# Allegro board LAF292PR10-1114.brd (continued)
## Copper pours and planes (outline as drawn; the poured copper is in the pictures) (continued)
+VREFCA on IN1 (solid shape): outline of 589 points within 136.57,34.88 153.97,38.31
+VREFDQ_A on BOTTOM (solid shape): 92.5,42.5 92.97,42.5 93.09,42.63 93.6,42.63 93.6,42.63 93.68,42.55 93.68,40.8 93.6,40.73 93.13,40.73 92.63,41.23 91.3,41.23 91.22,41.27 91.2,41.36 91.22,41.46 91.23,41.56 91.23,42.55 91.23,42.63 91.36,42.76 92.25,42.76
+VREFDQ_A on IN3 (solid shape): outline of 972 points within 92.5,33.37 119.93,43.77
BST_3V on TOP (solid shape): 73.89,43.19 73.89,42.33 73.81,42.25 72.89,42.25 72.73,42.09 71.75,42.09 71.61,42.23 71.61,42.92 71.95,43.27 73.82,43.27
BST_3V on BOTTOM (solid shape): 72.98,43.31 72.98,43.16 72.94,43.12 72.91,43.08 72.91,42.27 72.71,42.08 71.71,42.08 71.61,42.18 71.61,42.94 72.05,43.38 72.9,43.38
BST_5V on TOP (solid shape): 50.59,69.81 50.59,68.54 50.46,68.41 49.45,68.41 49.32,68.54 49.32,69.55 49.7,69.94 50.46,69.94
BST_5V on BOTTOM (solid shape): 51.13,70.25 51.13,70.11 51.11,70.07 51.09,70.02 50.91,69.83 50.91,69.45 50.78,69.33 49.57,69.33 49.48,69.41 49.48,70.06 49.73,70.31 51.08,70.31
BST_+1VALWP on BOTTOM (solid shape): 59.92,71.73 61.34,71.73 61.43,71.64 61.43,71.52 61.32,71.41 60.3,71.41 59.99,71.09 59.35,71.09 59.28,71.16 59.28,71.72 59.31,71.75 59.9,71.75
BST_+1VALWP_C on BOTTOM (solid shape): 58.95,71.74 58.95,71.07 59.04,70.97 59.04,70.37 58.93,70.25 58.48,70.25 58.34,70.39 58.34,71.72 58.46,71.84 58.84,71.84
CPU_B+ on TOP (solid shape): 82.03,65.47 82.03,65.14 81.33,64.44 81.33,63.69 81.46,63.57 81.46,62.52 81.34,62.4 79.4,62.4 79.26,62.54 79.26,65.6 80.39,66.73 80.78,66.73
CPU_B+ on TOP (solid shape): 90.49,80.32 92.52,80.32 92.64,80.19 92.64,77.27 92.44,77.07 90.97,77.07 90.64,76.73 90.64,76.72 90.44,76.53 90.44,74.22 90.19,73.98 88.63,73.98 88.41,74.19 88.41,79.67 89.07,80.32 90.49,80.32
CPU_B+ on BOTTOM (solid shape): 92.65,80.21 92.65,78.07 91.63,77.05 90.85,77.05 90.4,76.61 90.4,73.98 89.26,73.98 89.24,74 89.24,75.35 89.01,75.59 88.17,75.59 88.05,75.71 88.05,77.39 88.04,77.39 88.04,78 87.82,78.23 86.5,78.23 83.93,75.65 83.93,73.23 83.46,72.77 80.56,72.77 80.49,72.83 80.49,76.07 83.5,79.09 83.52,79.09 83.52,79.1 84.74,80.32 92.54,80.32
CPU_B+ on BOTTOM (solid shape): outline of 124 points within 66.84,54.04 85.89,67.41
CPU_B+ on IN1 (solid shape): 90.45,78.36 90.45,74.23 90.2,73.98 89.15,73.98 89.05,74.08 89.05,78.68 89.14,78.76 90.05,78.76
CPU_B+ on IN2 (solid shape): 90.45,78.36 90.45,74.23 90.2,73.98 89.16,73.98 89.05,74.08 89.05,78.68 89.14,78.76 90.05,78.76
CPU_B+ on IN3 (solid shape): 90.45,78.36 90.45,74.23 90.2,73.98 89.15,73.98 89.05,74.07 89.05,78.68 89.14,78.76 90.05,78.76
CPU_B+ on IN4 (solid shape): outline of 373 points within 77.56,62.4 90.64,79.33
DCIN_ISL9538 on TOP (solid shape): 54.24,34.89 54.24,34.1 53.62,33.49 53.38,33.49 53.26,33.61 53.26,34.12 54.07,34.93 54.2,34.93
GPU_B+ on TOP (solid shape): 84.54,58.67 87.12,58.67 88.08,59.63 90.43,59.63 90.65,59.41 90.65,58.4 90.5,58.25 89.33,58.25 89.14,58.06 89.14,57.16 88.84,56.86 82.96,56.86 81.65,58.18 77.76,58.18 77.52,58.42 77.52,59.43 77.72,59.63 83.59,59.63
GPU_B+ on BOTTOM (solid shape): 76.53,60.04 78.05,60.04 78.58,59.51 78.58,59.5 80.06,58.03 81.26,58.03 81.87,58.63 87.1,58.63 87.2,58.73 87.2,58.74 88.08,59.62 90.38,59.62 90.54,59.46 90.54,58.33 90.46,58.25 89.14,58.25 88.97,58.08 88.97,57.26 88.06,56.36 86.44,56.36 86.44,57.16 85.68,57.16 85.68,56.36 82.36,56.36 81.96,55.96 77.7,55.96 73.76,59.9 75.11,61.25 75.32,61.25
GPU_B+ on IN1 (solid shape): 86.21,59.44 90.5,59.44 90.65,59.29 90.65,58.4 90.46,58.21 77.86,58.21 77.61,58.46 77.61,59.32 77.73,59.44 86.21,59.44
GPU_B+ on IN2 (solid shape): 86.21,59.44 90.53,59.44 90.64,59.32 90.64,58.4 90.46,58.21 77.86,58.21 77.61,58.46 77.61,59.32 77.73,59.44 86.21,59.44
GPU_B+ on IN3 (solid shape): 86.21,59.44 90.54,59.44 90.63,59.35 90.63,58.42 90.43,58.21 77.86,58.21 77.61,58.46 77.61,59.32 77.73,59.44 86.21,59.44
GPU_B+ on IN4 (solid shape): 86.21,59.44 90.52,59.44 90.63,59.33 90.63,58.39 90.45,58.21 77.86,58.21 77.61,58.46 77.61,59.32 77.73,59.44 86.21,59.44
GT_SNUB on TOP (solid shape): 93.36,63.71 93.36,63.24 96.21,60.39 96.21,58.76 96.12,58.68 95.18,58.68 94.1,59.76 94.1,61.1 92.15,63.05 92.15,63.7 92.28,63.83 93.24,63.83
GT_SW on TOP (solid shape): 97.44,61.62 97.44,60.86 97.76,60.54 98.79,60.54 98.9,60.43 98.9,58.73 98.83,58.67 97.8,58.67 96.34,60.13 96.34,61.64 96.47,61.77 97.3,61.77
GT_SW on BOTTOM (solid shape): 95.44,63.91 96.09,63.91 97.79,62.21 97.79,58.82 96.83,58.82 96.83,57.96 97.77,57.96 97.77,56.57 95.41,56.57 95.32,56.67 95.32,59.97 94.64,60.65 92.82,60.65 92.82,60.65 92.65,60.65 92.64,60.66 92.64,61.93 92.45,62.12 88.67,62.12 88.63,62.15 88.63,63.28 88.96,63.61 90.08,63.61 90.4,63.93 95.42,63.93
IA_SNUB1 on BOTTOM (solid shape): 90.94,83.24 90.94,81.57 90.87,81.5 89.09,81.5 88.89,81.7 88.89,83.13 89.07,83.31 90.88,83.31
IA_SNUB2 on BOTTOM (solid shape): 82.98,71.63 82.98,69.27 82.8,69.09 81.57,69.09 81.37,69.28 81.37,71.67 81.48,71.77 82.83,71.77
IA_SW1 on BOTTOM (solid shape): 93.67,83.12 93.67,82.44 94.86,81.26 97.51,81.26 97.51,79.65 97.31,79.45 97.31,78.18 96.36,78.18 96.36,77.29 97.31,77.29 97.31,71.99 95.79,70.47 92.07,70.47 91.59,70.94 91.59,71.87 91.63,71.91 92.82,71.91 93.06,72.15 93.06,75.79 93.2,75.94 93.84,75.94 94.88,76.97 94.88,79.74 94.88,79.95 93.26,81.56 92.59,81.56 92.55,81.6 92.55,83.2 92.59,83.25 93.54,83.25
IA_SW2 on BOTTOM (solid shape): 85.33,71.64 85.33,70.5 85.54,70.29 85.55,70.29 85.59,70.25 88.06,70.25 88.13,70.24 88.2,70.25 88.27,70.25 88.31,70.29 88.35,70.29 88.45,70.39 88.77,70.39 89.36,69.8 90.45,69.8 91.46,68.79 93.06,68.79 93.06,67.44 92.11,67.44 92.11,66.62 93.06,66.62 93.06,65.24 92.96,65.15 90.39,65.15 90.24,65.3 90.24,67.18 89.93,67.48 88.98,67.48 88.83,67.33 88,67.33 87.96,67.38 87.96,68.64 87.81,68.78 84.08,68.78 83.96,68.9 83.96,71.72 84.09,71.84 85.13,71.84
INT_SPK_L+ on TOP (solid shape): 291.49,25.25 291.49,24.78 291.36,24.65 289.5,24.65 289.43,24.57 288.87,24.57 288.84,24.6 288.84,25.23 288.97,25.36 291.38,25.36
INT_SPK_L+ on TOP (solid shape): 268.27,40.13 268.27,39.18 267.5,38.41 267.5,37.55 267.45,37.5 267.33,37.5 267.23,37.6 267.23,38.59 267.76,39.12 267.76,40.19 267.82,40.26 268.14,40.26
INT_SPK_L+ on IN1 (solid shape): 291.51,25.23 291.51,24.6 291.38,24.47 289.48,24.47 289.35,24.34 288.97,24.34 288.84,24.47 288.84,25.23 288.97,25.36 291.38,25.36
INT_SPK_L+ on IN1 (solid shape): 268.29,40.19 268.29,39.07 267.61,38.39 267.61,37.5 267.45,37.35 266.92,37.35 266.79,37.47 266.79,38.54 266.9,38.64 267.38,38.64 267.76,39.02 267.76,40.14 267.89,40.27 268.22,40.27
INT_SPK_L- on TOP (solid shape): 267.63,39.96 267.63,39.33 267.1,38.79 267.1,37.55 267.05,37.5 266.9,37.5 266.84,37.55 266.84,38.85 267.12,39.12 267.12,39.96 267.25,40.09 267.5,40.09
INT_SPK_L- on TOP (solid shape): 291.23,22.67 291.23,22.22 291.32,22.13 291.32,21.26 291.14,21.08 290.93,21.08 290.89,21.12 290.89,21.4 290.87,21.55 290.83,21.68 290.83,21.69 290.83,22 290.27,22.56 289.04,22.56 288.84,22.77 288.84,23.48 288.94,23.58 290.32,23.58
INT_SPK_L- on IN1 (solid shape): 291.46,22 291.46,21.23 291.35,21.11 289.51,21.11 289.38,21.24 289.38,22 289.63,22.25 291.21,22.25
INT_SPK_L- on IN1 (solid shape): 267.63,40.47 267.63,39.1 267.48,38.95 267.1,38.95 267,39.05 267,39.96 266.87,40.09 265.6,40.09 265.47,40.22 265.47,41.11 265.6,41.23 266.87,41.23
INT_SPK_R+ on TOP (solid shape): 299,25.1 299,23.33 297.86,23.33 297.86,25.17 297.92,25.23 298.87,25.23
INT_SPK_R+ on TOP (solid shape): 266.21,39.61 266.21,38.69 266.29,38.62 266.29,37.58 266.21,37.5 266.16,37.5 266.06,37.6 266.06,38.39 265.73,38.72 265.73,39.58 265.85,39.71 266.11,39.71
INT_SPK_R+ on IN2 (solid shape): 299,25.1 299,24.22 298.87,24.09 297.1,24.09 296.97,24.22 296.97,25.1 297.1,25.23 298.87,25.23
INT_SPK_R+ on IN2 (solid shape): 266.18,39.56 266.18,38.74 266.08,38.64 265.8,38.64 264.71,37.55 264.58,37.55 264.2,37.93 264.2,38.14 264.41,38.36 264.53,38.49 264.61,38.64 265.66,39.68 266.06,39.68
INT_SPK_R- on TOP (solid shape): 299.08,22.72 299.08,20.99 298.75,20.66 298.19,20.66 297.96,20.89 297.96,22.7 298.08,22.82 298.98,22.82
INT_SPK_R- on TOP (solid shape): 267,39.84 267,39.18 266.72,38.9 266.72,37.52 266.67,37.47 266.54,37.47 266.46,37.55 266.46,38.74 266.36,38.85 266.36,39.84 266.49,39.96 266.87,39.96
INT_SPK_R- on IN2 (solid shape): 299,22.06 299,20.91 298.87,20.79 297.1,20.79 296.97,20.91 296.97,22.06 297.1,22.18 298.87,22.18
INT_SPK_R- on IN2 (solid shape): 267,40.47 267,38.82 266.87,38.69 266.49,38.69 266.39,38.79 266.39,39.61 266.03,39.96 265.22,39.96 264.44,39.18 264.42,39.18 264.13,39.08 263.87,38.89 263.81,38.83 263.62,38.83 263.31,39.14 263.31,39.58 264.58,40.85 266.62,40.85
INT_SPKR_L+ on TOP (solid shape): 288.59,25.28 288.59,24.47 288.33,24.22 287.87,24.22 285.54,24.22 285.03,23.71 283.76,23.71 283.06,23.01 283.06,21.73 282.88,21.55 282.11,21.55 281.86,21.8 281.86,23.71 283.63,25.49 288.38,25.49
INT_SPKR_L+ on BOTTOM (solid shape): 283.03,23.04 283.03,17.99 282.78,17.74 281.34,17.74 281.27,17.81 281.27,23 281.27,23.12 281.39,23.24 282.83,23.24
INT_SPKR_L- on TOP (solid shape): 288.59,23.47 288.59,22.56 287.19,21.17 285.16,21.17 284.9,20.91 284.9,20.02 284.65,19.77 283.89,19.77 283.6,20.06 283.6,22.72 283.91,23.03 284.82,23.03 285.28,22.56 286.94,22.56 287.95,23.58 288.47,23.58
INT_SPKR_L- on BOTTOM (solid shape): 285.03,21.42 285.03,16.98 284.52,16.47 282.24,16.47 281.86,16.85 281.86,17.36 281.98,17.48 283.51,17.48 283.89,17.87 283.89,21.42 284.01,21.55 284.91,21.55
INT_SPKR_R+ on TOP (solid shape): 297.63,25.21 297.63,24.24 297.35,23.96 296.81,23.96 296.39,23.96 296.25,24.1 294.44,24.1 294.17,23.83 293.42,23.83 292.74,23.15 292.74,22.2 293.04,21.9 293.04,20.99 292.86,20.81 292,20.81 291.83,20.98 291.83,22.73 291.72,22.83 291.72,24.05 292.8,25.13 296.5,25.13 296.86,25.49 297.35,25.49
INT_SPKR_R+ on BOTTOM (solid shape): 293.06,21.19 293.01,21.14 293.01,20.9 292.62,20.51 292.56,20.46 292.51,20.42 291.65,19.55 291.12,19.02 290.8,19.34 290.8,20.15 291.98,21.34 292.91,21.34
INT_SPKR_R- on TOP (solid shape): 295.7,22.06 297.48,22.06 297.61,22.06 297.74,21.92 297.74,21.19 297.46,20.91 296.6,20.91 296.04,21.17 295.48,20.93 295.46,20.91 295.37,20.91 295.36,20.92 295.11,20.97 294.87,20.92 294.86,20.91 294.81,20.91 294.56,20.66 294.56,20.5 294.55,20.45 294.55,20.41 294.33,20.19 293.55,20.19 293.47,20.28 293.47,21.66 292.87,22.26 292.87,22.73 293.21,23.07 294.68,23.07
INT_SPKR_R- on BOTTOM (solid shape): 294.67,21.22 294.67,20.41 293.66,19.4 293.66,19.38 293.16,18.88 293.03,18.88 292.78,19.14 292.78,19.95 293.63,20.8 293.63,20.88 293.63,21.29 293.86,21.52 294.38,21.52
LG1_ISL9538 on TOP (solid shape): 53.45,38.31 53.6,38.31 53.93,37.98 53.93,37.92 53.85,37.84 53.13,37.84 52.7,38.26 52.7,38.29 52.24,38.75 52.24,38.76 52.23,38.76 52.17,38.82 52.11,38.82 51.99,38.95 51.99,39.2 52.16,39.38 52.38,39.38
LG1_ISL9538 on BOTTOM (solid shape): 45.94,52.4 45.94,49.35 45.78,49.19 45.1,49.19 44.95,49.34 44.95,52.4 45,52.45 45.89,52.45
LG1_ISL9538 on IN3 (solid shape): 53.13,38.88 53.13,38.57 52.75,38.19 52.3,38.19 50.91,39.58 50.91,39.84 51.41,40.34 51.67,40.34
LG1_ISL9538 on IN3 (solid shape): 51.5,49.4 51.52,49.4 52.98,47.94 52.98,47.15 52.84,47.01 52.05,47.01 51.91,47.15 51.91,47.49 51.03,48.37 50.88,48.37 50.63,48.62 50.63,49.45 50.79,49.62 51.29,49.62
LG1_ISL9538 on IN4 (solid shape): 47.15,50.16 47.15,49.37 46.91,49.13 45.64,49.13 45.5,49.27 45.5,50.16 45.57,50.24 47.07,50.24
LG1_ISL9538 on IN4 (solid shape): 51.24,49.7 51.24,48.62 50.99,48.38 50.7,48.38 49.99,49.08 49.34,49.08 49.23,49.2 49.23,50.03 49.3,50.1 50.16,50.1 50.17,50.11 50.83,50.11
LG2_ISL9538 on TOP (solid shape): 53.84,39.58 54.09,39.58 54.64,39.03 54.64,38.21 54.58,38.14 54.5,38.14 54.43,38.21 54.43,38.92 54.36,38.99 54.36,39 54.22,39.14 54.03,39.13 54.02,39.12 53.94,39.12 53.83,39.01 53.64,39.01 53.07,39.58 53.07,39.77 53.26,39.96 53.46,39.96
LG2_ISL9538 on BOTTOM (solid shape): 65.94,49.48 66.38,49.48 66.41,49.44 66.41,47.82 66.31,47.72 65.73,47.72 65.03,48.42 65.03,49.88 65.12,49.97 65.45,49.97
LG2_ISL9538 on IN3 (solid shape): 66.32,49.22 66.32,47.52 66.11,47.3 65.41,47.3 65.21,47.51 65.21,48.66 64.95,48.92 64.95,49.81 65.17,50.02 65.52,50.02
LG2_ISL9538 on IN3 (solid shape): 56.47,41.68 56.48,41.68 56.67,41.49 56.67,41.23 55.96,40.53 54.76,40.53 54.39,40.15 54.39,39.51 54.32,39.45 54.32,39.44 53.85,38.97 53.67,38.97 53.06,39.58 53.06,39.77 53.36,40.06 53.36,40.78 54.26,41.68 55.57,41.68 55.93,42.04 56.11,42.04
LINE1_R on TOP (solid shape): 271.71,36.09 271.71,35.99 271.44,35.72 271.12,35.72 271.04,35.81 269.83,35.81 269.78,35.86 269.78,35.95 269.85,36.03 271.14,36.03 271.37,36.25 271.54,36.25
LX1_ISL9538 on TOP (solid shape): 55.5,53.34 55.5,50.81 55.44,50.75 54.08,50.75 53.93,50.9 53.93,53.83 54.25,54.15 54.69,54.15
LX1_ISL9538 on TOP (solid shape): 51.35,38.69 52.11,38.69 52.57,38.24 52.57,38.21 52.94,37.85 52.94,37.84 52.98,37.78 53.05,37.73 53.05,37.73 53.14,37.64 53.87,37.64 53.93,37.58 53.93,37.5 53.87,37.44 53.04,37.44 52.67,37.8 52.58,37.8 52.49,37.82 52.4,37.8 52.24,37.8 52.05,37.61 51.03,37.61 50.84,37.8 50.84,38.69 50.97,38.82 51.22,38.82
LX1_ISL9538 on BOTTOM (solid shape): 47.24,57.13 47.24,56.28 47.18,56.22 46.45,56.22 46.41,56.25 46.41,56.87 46.29,56.99 45.9,56.99 45.79,57.1 45.79,57.31 45.95,57.46 46.91,57.46
LX1_ISL9538 on BOTTOM (solid shape): 55.29,55.05 55.29,48.47 54.91,48.09 47.08,48.09 46.31,48.85 46.31,51.27 46.44,51.39 50.05,51.39 50.59,51.93 50.59,52.56 50.72,52.69 51.85,52.69 52.08,52.92 52.08,55.14 52.41,55.46 54.88,55.46
LX1_ISL9538 on IN1 (solid shape): 51.48,37.8 51.35,37.68 50.46,37.68 50.33,37.8 50.33,40.47 51.48,40.47
LX1_ISL9538 on IN1 (solid shape): 47.76,58.05 47.76,57.43 47.68,57.35 47.08,57.35 46.72,56.98 45.83,56.98 45.73,57.08 45.73,58 46.11,58.38 47.43,58.38
LX1_ISL9538 on IN1 (solid shape): 54.16,56.45 54.16,54.6 55.2,53.55 55.2,52.32 54.51,51.63 54.13,51.63 53.75,52.02 53.75,53.18 53.14,53.79 53.14,56.45 53.22,56.54 54.06,56.54
LX2_ISL9538 on TOP (solid shape): 66.49,48.61 66.49,47.46 66.48,47.45 66.48,47.12 66.29,46.92 64.6,46.92 64.43,47.09 64.43,48.33 64.77,48.68 66.43,48.68
LX2_ISL9538 on TOP (solid shape): 54.4,40.85 54.4,39.84 54.54,39.7 54.58,39.65 54.63,39.61 55.04,39.19 55.04,38.2 54.98,38.14 54.9,38.14 54.84,38.2 54.84,39.02 54.77,39.09 54.77,39.11 54.37,39.51 54.35,39.51 54.15,39.71 53.89,39.71 53.51,40.09 53.18,40.09 53.03,39.94 52.85,39.94 52.27,40.52 52.27,41 52.37,41.11 54.14,41.11
LX2_ISL9538 on BOTTOM (solid shape): 67.76,54.4 67.76,53.33 67.7,53.27 66.85,53.27 66.68,53.44 66.68,54.37 66.83,54.52 67.64,54.52
LX2_ISL9538 on BOTTOM (solid shape): 64.56,52.66 64.56,48.32 65.45,47.43 66.54,47.43 66.9,47.79 66.9,48.32 66.98,48.41 70.16,48.41 70.22,48.35 70.22,45.18 69.26,44.22 64.95,44.22 63.98,45.19 66.03,45.19 66.03,45.14 66.04,45.09 66.06,45.04 66.09,44.99 66.12,44.95 66.16,44.91 66.21,44.88 66.25,44.86 66.31,44.84 66.36,44.84 66.41,44.84 66.46,44.84 66.52,44.86 66.56,44.88 66.61,44.91 66.65,44.95 66.68,44.99 66.71,45.04 66.73,45.09 66.74,45.14 66.74,45.19 66.74,45.25 66.73,45.3 66.71,45.35 66.68,45.39 66.65,45.44 66.61,45.47 66.56,45.5 66.52,45.52 66.46,45.54 66.41,45.55 66.36,45.55 66.31,45.54 66.25,45.52 66.21,45.5 66.16,45.47 66.12,45.44 66.09,45.39 66.06,45.35 66.04,45.3 66.03,45.25 66.03,45.19 63.98,45.19 62.6,46.57 60.49,46.57 59.99,47.07 59.99,51.45 59.99,52.66 60.11,52.79 64.43,52.79
LX2_ISL9538 on IN1 (solid shape): 55.29,41.49 55.29,41.11 54.27,40.09 52.68,40.09 52.24,40.53 52.24,40.73 53.26,41.74 55.03,41.74
LX2_ISL9538 on IN1 (solid shape): 67.11,55.81 67.34,55.63 67.63,55.68 67.66,55.71 67.75,55.62 67.75,54.14 67.61,54 66.76,54 66.67,54.09 66.67,55.79 66.69,55.81
LX2_ISL9538 on GND5: 60.37,47.2 60.37,49.11 61.66,49.11 62.17,48.6 62.17,47.31 62.07,47.2
LX_1.8VALW on TOP (solid shape): 213.78,30.69 213.78,29.8 214.29,29.3 214.29,27.14 214.04,26.88 212.89,26.88 212.64,27.14 212.64,29.68 212.51,29.8 211.5,29.8 211.24,30.06 211.24,30.57 211.65,30.97 213.5,30.97
LX_1V_PRIM on BOTTOM (solid shape): 165.17,31.47 165.17,30.18 165.08,30.09 165.08,27.42 164.67,27.01 161.94,27.01 161.61,27.34 161.61,29.83 161.84,30.06 163.7,30.06 164.42,30.78 164.42,31.47 164.5,31.55 165.1,31.55
LX_1VS_VCCIO on TOP (solid shape): 181.27,29.93 181.27,26.5 181.02,26.25 180.13,26.25 179.75,26.63 179.75,27.77 179.39,28.13 178.47,28.13 178.41,28.19 178.41,28.87 178.46,28.91 179.56,28.91 179.75,29.1 179.75,29.92 180.01,30.18 181.02,30.18
LX_3V on TOP (solid shape): 73.83,41.96 73.83,38.96 73.43,38.56 71.42,38.56 71.24,38.74 71.24,41.74 71.32,41.82 72.87,41.82 73.05,42 73.79,42
LX_3V on BOTTOM (solid shape): 73.76,42.99 73.76,41.68 74.34,41.11 75.61,41.11 75.74,40.98 75.74,38.31 75.48,38.06 71.8,38.06 71.26,38.59 71.26,41.77 71.32,41.82 72.65,41.82 73.06,42.23 73.06,42.97 73.13,43.05 73.7,43.05
LX_5V on BOTTOM (solid shape): 51.91,70.01 51.91,68.23 53.13,67.01 54.53,67.01 54.65,66.89 54.65,63.51 54.56,63.41 50.63,63.41 49.45,64.6 49.45,68.67 49.7,68.92 50.84,68.92 51.22,69.3 51.22,69.94 51.35,70.06 51.86,70.06
LX_DDR on TOP (solid shape): 85.13,37.8 85.13,36.79 85.01,36.66 84.62,36.66 83.48,35.52 81.58,35.52 81.45,35.65 81.45,36.41 81.58,36.53 82.34,36.53 82.72,36.92 82.72,37.93 82.85,38.06 84.88,38.06
LX_DDR on BOTTOM (solid shape): 85.21,43.13 85.21,41.16 86.4,39.96 86.4,38.19 84.88,36.66 82.59,36.66 82.11,37.14 82.11,39.99 82.59,40.47 83.35,40.47 83.86,40.98 83.86,43.12 83.9,43.16 85.18,43.16
Net_33 on TOP (solid shape): 293.19,8.02 281.19,8.02 281.19,16.02 293.19,16.02
PBATT+_C on TOP (solid shape): 59.86,51.27 59.86,48.17 62.37,45.66 62.37,44.25 61.71,43.58 60.4,43.58 60.22,43.77 60.22,44.31 60.21,44.31 60.21,44.65 59.22,45.65 58.3,45.65 56.94,47.01 56.94,51.27 57.19,51.52 59.61,51.52
PBATT+_C on BOTTOM (solid shape): 59.86,51.39 59.86,46.98 60.46,46.38 61.54,46.38 61.82,46.1 61.82,45.12 61.82,43.74 61.82,41.58 61.1,40.86 56.38,40.86 56.11,41.12 56.11,42.03 56.61,42.53 57.09,42.53 57.29,42.73 57.29,44.81 56.94,45.17 56.94,51.27 57.45,51.77 59.48,51.77
PBATT+_C on IN2 (solid shape): 60.04,51.12 60.04,48.03 62.09,45.99 62.13,45.93 62.18,45.88 62.18,43.96 61.79,43.58 59.67,43.58 56.65,46.6 56.65,50.96 57.52,51.83 59.33,51.83
PBATT+_C on IN4 (solid shape): 59.86,51.27 59.86,48.92 59.87,48.91 59.87,46.67 59.5,46.3 57.28,46.3 56.94,46.64 56.94,51.14 57.19,51.39 57.45,51.39 57.83,51.77 59.35,51.77
PBATT+_C on GND1, GND5: 58.19,46.31 56.94,47.56 56.94,51.03 57.68,51.77 59.37,51.77 59.86,51.29 59.86,47.05 59.12,46.31
RING2 on TOP (solid shape): 279.7,39.46 279.7,38.44 279.57,38.31 278.05,38.31 277.79,38.57 277.79,39.46 277.92,39.58 279.57,39.58
RING2 on TOP (solid shape): 271.75,34.11 271.75,33.81 271.67,33.73 271.44,33.73 271.09,34.08 270.94,34.08 270.79,34.22 269.81,34.22 269.77,34.26 269.77,34.4 269.81,34.43 270.82,34.43 270.93,34.55 271.32,34.55
RING2 on IN1 (solid shape): 279.06,39.07 279.06,33.99 276.52,31.45 272.71,31.45 270.43,33.74 270.43,34.63 270.68,34.88 271.82,34.88 272.97,33.74 276.01,33.74 276.68,34.4 276.68,34.41 276.76,34.47 276.82,34.54 276.82,34.55 277.28,35.01 277.28,38.95 277.79,39.46 278.68,39.46
RING2_R on TOP (solid shape): 280.97,41.49 281.35,41.11 283.7,41.11 283.76,41.05 284.21,41.05 285.16,40.11 285.16,39.58 284.87,39.29 282.66,39.29 281.98,39.96 281.22,39.96 281.2,39.96 280.69,39.96 280.67,39.96 279.82,39.96 279.7,39.84 278.68,39.84 278.55,39.96 278.55,41.74 278.81,42 280.46,42
RING2_R on IN1 (solid shape): 285.57,39.68 295.35,39.68 296.68,38.34 296.68,37.65 296.71,37.61 296.71,36.92 296.46,36.66 295.06,36.66 293.92,37.8 284.01,37.8 282.11,39.71 282.11,40.73 282.62,41.23 284.02,41.23
SA_LGATE on BOTTOM (solid shape): 87.23,49.54 87.23,49.19 87.13,49.09 85.31,49.09 85.22,49.18 85.22,49.55 85.27,49.6 87.16,49.6
SA_LGATE on IN2 (solid shape): 88.73,55.97 88.73,55.34 87.61,54.21 87.23,54.21 86.91,54.53 86.91,54.59 87.68,55.36 87.68,55.86 87.68,55.86 87.68,55.93 87.85,56.1 88.6,56.1
SA_LGATE on IN2 (solid shape): 85.46,49.8 85.67,49.59 86.15,49.59 86.27,49.48 86.27,49.04 86.17,48.94 85.07,48.94 84.69,49.32 84.69,50.48 84.75,50.54 85.46,50.54
SA_LGATE on GND5 (solid shape): 88.75,55.98 88.75,55.05 88.58,54.88 87.83,54.88 87.7,55.01 87.7,55.98 87.83,56.12 88.61,56.12
SA_SNUB on TOP (solid shape): 98.01,56.76 98.01,55.77 97.95,55.71 96.2,55.71 96.19,55.71 95.93,55.71 94.01,53.79 92.53,53.79 92.47,53.86 92.47,55.46 92.47,55.46 93.56,55.46 94.9,56.81 97.96,56.81
SA_SW on TOP (solid shape): 90.9,55.43 90.9,53.44 90.34,52.88 88.96,52.88 88.18,53.66 88.18,54.3 88.28,54.41 88.71,54.41 89.78,55.48 90.85,55.48
SA_SW on BOTTOM (solid shape): 87.53,51.63 87.53,51.29 87.24,51 87.24,50.92 87.11,50.79 86.52,50.79 86.41,50.9 86.41,51.64 86.52,51.75 87.42,51.75
SA_SW on BOTTOM (solid shape): 88.5,54.38 90.85,54.38 90.85,54.4 92.25,54.4 92.75,53.9 92.75,52.18 91.81,52.18 91.81,51.33 92.75,51.33 92.75,50.25 92.64,50.14 90.45,50.14 90.2,50.39 90.2,51.63 88.26,53.58 85.72,53.58 85.71,53.59 85.55,53.59 85.49,53.65 85.49,54.63 85.52,54.66 88.22,54.66
SA_SW on IN1 (solid shape): 90.36,53.29 90.36,52.12 89.18,50.93 86.61,50.93 86.44,51.1 86.44,51.8 86.63,51.99 88.75,51.99 89.25,52.49 89.25,52.5 89.33,52.58 89.33,53.3 89.38,53.35 90.31,53.35
SA_UGATE on BOTTOM (solid shape): 89.42,51.78 89.42,50.89 89.34,50.81 88.68,50.81 88.54,50.95 88.54,51.24 88.1,51.67 87.82,51.67 87.52,51.97 87.52,52.46 87.63,52.57 88.63,52.57
SLEEVE on TOP (solid shape): 278.93,37.8 278.93,36.81 278.93,36.81 278.93,35.98 278.93,35.98 278.93,35.09 278.93,35.07 278.93,34.38 276.77,32.21 274.45,32.21 273.77,32.88 273.77,32.9 273.68,33.07 273.51,33.16 273.49,33.16 273.46,33.19 272.19,33.19 271.86,33.52 271.86,34.16 271.42,34.6 271.38,34.6 271.35,34.64 270.9,34.64 270.87,34.6 269.84,34.6 269.78,34.67 269.78,34.78 269.83,34.83 270.09,34.83 270.16,34.81 270.22,34.8 270.79,34.8 270.87,34.88 271.82,34.88 272.11,34.59 272.11,34.18 272.13,34.18 272.13,34.12 272.2,34.04 274.06,34.04 274.62,33.49 276.23,33.49 277.61,34.87 277.61,37.64 277.9,37.93 278.81,37.93
SLEEVE_R on TOP (solid shape): 294.1,37.8 294.1,36.79 293.89,36.58 292.48,36.58 292.27,36.79 292.27,37.8 291.82,38.24 285.87,38.24 285.34,37.71 282.57,37.71 282.1,37.23 282.1,37.06 281.65,36.61 279.5,36.61 279.19,36.92 279.19,37.8 279.29,37.91 280.94,37.91 282.03,39 284.83,39 284.87,39.04 284.97,39.04 285.41,39.48 285.41,39.52 292.38,39.52
SNB_+1VALWP on BOTTOM (solid shape): 57.45,64.77 57.45,62.99 57.19,62.73 55.92,62.73 55.67,62.99 55.67,64.77 55.8,64.89 57.32,64.89
SNUB_1V_PRIM on BOTTOM (solid shape): 160.94,28.47 160.94,27.61 160.75,27.42 159.39,27.42 159.19,27.62 159.19,28.44 159.34,28.6 160.81,28.6
SNUB_CHG1 on TOP (solid shape): 52.99,53.83 52.99,50.85 52.84,50.69 51.86,50.69 51.71,50.85 51.71,53.67 52,53.96 52.86,53.96
SNUB_CHG2 on TOP (solid shape): 69.83,48.53 69.83,47.01 67.84,47.01 67.73,47.11 67.73,48.6 67.84,48.7 69.66,48.7
SW_+1VALWP on BOTTOM (solid shape): 61.75,74.42 61.75,73.67 61.69,73.61 61.56,73.61 61.35,73.82 60.89,73.82 60.39,74.32 60.39,74.62 60.48,74.71 61.46,74.71
SW_+1VALWP on BOTTOM (solid shape): 62.21,71.31 62.21,69.31 62.7,68.82 62.7,67.32 62.15,66.76 59.1,66.76 58.34,66 56.3,66 55.67,66.63 55.67,67.52 55.8,67.65 57.19,67.65 58.46,68.92 58.46,69.17 59.17,69.88 59.17,69.89 59.2,69.92 59.2,70.85 59.24,70.89 60.04,70.89 60.37,71.22 61.41,71.22 61.56,71.37 62.15,71.37
SW_+1VALWP on IN2 (solid shape): 61.36,74.59 61.36,70.52 61.23,70.39 60.44,70.39 60.22,70.62 60.22,74.65 60.34,74.78 61.17,74.78
TBTA_DC_SS on TOP (solid shape): 50.56,80.27 50.56,77.68 50.31,77.43 48.41,77.43 48.33,77.47 48.31,77.56 47.97,78.01 47.63,77.56 47.61,77.47 47.53,77.43 46.52,77.43 46.21,77.74 43.92,77.74 43.73,77.92 43.73,78.22 43.86,78.49 43.73,78.77 43.73,79.97 43.91,80.15 47.43,80.15 47.59,80.3 50.53,80.3
TBTA_DC_SS on BOTTOM (solid shape): 48.68,80.6 48.68,78.32 48.25,77.88 48.12,77.98 47.96,78.01 47.62,77.77 47.74,77.38 47.67,77.3 44.87,77.3 44.42,77.75 44.42,80.84 44.44,80.86 48.43,80.86
TBTA_DC_SS on IN3 (solid shape): 48.18,78.95 48.18,78.06 48.1,77.99 48.07,78 47.72,77.91 47.63,77.56 47.64,77.53 47.54,77.43 45.25,77.43 45.25,78.06 45.76,78.57 45.76,78.57 46.27,79.08 48.05,79.08
TBTB_DC_SS on TOP (solid shape): 45.7,50.43 45.7,48.71 46.02,48.4 46.02,48.39 46.95,47.46 46.96,47.46 47.41,47 47.41,45.05 46.61,44.25 44.38,44.25 44.3,44.33 44.3,46.38 43.35,47.33 43.35,50.38 43.48,50.5 45.62,50.5
TBTB_DC_SS on BOTTOM (solid shape): 46.75,47.68 46.75,45.91 45.89,45.04 43.22,45.04 43.06,45.21 43.06,47.04 43.22,47.2 44.62,47.2 44.62,47.21 45.2,47.21 45.83,47.84 46.6,47.84
TBTB_DC_SS on IN1 (solid shape): 46.92,47.63 46.92,46.15 46.7,45.93 46.15,45.93 45.7,46.38 45.7,47.65 45.84,47.79 46.76,47.79
UG1_ISL9538 on TOP (solid shape): 52.97,37.31 52.99,37.31 53.06,37.24 53.87,37.24 53.93,37.18 53.93,37.1 53.87,37.04 53.07,37.04 53,36.97 52.94,36.97 52.77,36.79 52.75,36.79 52.62,36.66 52.37,36.66 52.24,36.79 52.24,37.55 52.37,37.68 52.6,37.68
UG1_ISL9538 on IN1 (solid shape): 52.75,37.55 52.75,36.53 52.49,36.28 51.73,36.28 51.01,36.28 50.95,36.34 50.95,37.02 51.22,37.3 51.86,37.3 52.24,37.68 52.62,37.68
UG1_ISL9538 on IN1 (solid shape): 47.99,56.92 47.99,56.09 47.89,55.99 47.21,55.99 46.67,55.45 45.94,55.45 45.71,55.67 45.71,56.46 45.87,56.62 45.88,56.62 46.05,56.79 46.77,56.79 46.99,57.02 47.88,57.02
UG1_ISL9538 on GND5 (solid shape): 46.21,56.41 46.21,55.63 46.13,55.55 45.59,55.55 45.33,55.81 45.33,56.71 45.49,56.87 45.75,56.87
UG2_ISL9538 on TOP (solid shape): 55.07,40.07 55.12,40.03 55.18,40 55.49,39.68 55.49,39.1 55.44,39.05 55.44,38.2 55.38,38.14 55.3,38.14 55.24,38.2 55.24,39.13 55.21,39.15 55.21,39.2 54.58,39.84 54.58,40.01 54.7,40.14 55.01,40.14
UG2_ISL9538 on BOTTOM (solid shape): 66.46,54.39 66.46,54.15 66.4,54.09 66.4,53.3 66.27,53.17 65.77,53.17 65.64,53.3 65.64,53.95 65.41,54.18 65.41,54.39 65.53,54.51 66.34,54.51
UG2_ISL9538 on IN1 (solid shape): 56.8,40.36 56.8,40.2 55.8,39.2 55.16,39.2 54.53,39.84 54.53,39.96 54.78,40.22 55.29,40.22 55.35,40.22 56.01,40.88 56.28,40.88
UG2_ISL9538 on IN1 (solid shape): 66.45,54.43 66.45,53.71 65.66,52.92 65.35,52.92 64.97,53.3 64.97,53.62 65.31,53.96 65.31,53.99 65.35,54.03 65.35,54.43 65.47,54.54 66.33,54.54
N16775433 on TOP (solid shape): 86.48,37.98 86.48,35.26 85.39,35.26 85.26,35.39 85.26,37.93 85.45,38.12 86.34,38.12
N16775517 on TOP (solid shape): 82.39,39.52 82.39,36.97 82.26,36.84 81.57,36.84 81.51,36.89 81.51,37.78 81.24,38.05 81.24,39.93 81.36,40.05 81.86,40.05
N16775517 on BOTTOM (solid shape): 83.31,41.82 83.31,41.3 82.61,40.6 82.54,40.6 81.98,40.04 81.98,39.12 81.82,38.96 81.45,38.96 81.25,39.16 81.25,40.41 81.65,40.81 81.65,40.92 82.31,41.58 82.31,41.81 82.42,41.92 83.22,41.92
N16783014 on BOTTOM (solid shape): 75.48,42.63 77.51,42.63 78.4,41.74 79.36,41.74 79.42,41.74 79.52,41.64 79.52,41.05 78.07,41.05 77.39,41.74 74.9,41.74 74.41,42.23 74.41,42.98 74.48,43.05 75.06,43.05
N16783222 on BOTTOM (solid shape): 53.33,69.83 53.42,69.83 53.83,69.43 54.27,69.43 54.78,68.92 55.54,68.92 55.67,68.79 55.67,68.03 55.54,67.9 54.4,67.9 53.64,68.67 53.06,68.67 52.56,69.16 52.56,69.91 52.62,69.97 53.19,69.97
N39469798 on BOTTOM (solid shape): 85.88,51.19 85.88,50.87 86.15,50.59 87.15,50.59 87.19,50.55 87.19,50.4 87.11,50.32 86.02,50.32 85.79,50.55 85.35,50.55 85.21,50.69 85.21,51.28 85.24,51.31 85.75,51.31
N39469996 on TOP (solid shape): 87.89,54.3 87.89,53.28 90.4,50.77 90.4,50.61 90,50.2 89.75,50.2 86.9,53.06 86.9,54.25 86.97,54.32 87.86,54.32
N39469998 on TOP (solid shape): 89.09,55.68 89.09,55.07 89.06,55.04 86.96,55.04 86.94,55.07 86.94,55.69 89.08,55.69
N47324022 on BOTTOM (solid shape): 63.82,71.04 63.82,70.28 64.18,69.92 64.18,69.05 63.99,68.86 63.35,68.86 63.29,68.92 63.29,70.1 62.84,70.55 62.84,71.31 62.91,71.37 63.49,71.37
N49223737 on BOTTOM (solid shape): 87.85,75.84 87.85,75.67 88.12,75.4 88.82,75.4 88.92,75.3 88.92,75.15 88.86,75.1 88.08,75.1 87.99,75 87.03,75 86.96,75.07 86.96,75.97 87.03,76.05 87.64,76.05
N49223739 on BOTTOM (solid shape): 88.15,74.4 88.82,74.4 88.92,74.3 88.92,74.15 88.84,74.08 87.85,74.08 87.65,73.88 87,73.88 86.98,73.9 86.98,74.74 87.05,74.82 87.73,74.82
N49223741 on BOTTOM (solid shape): 86.29,75.98 86.29,73.89 86.24,73.85 85.66,73.85 85.56,73.94 85.56,75.98 85.62,76.04 86.23,76.04
N49227484 on BOTTOM (solid shape): 84.81,64.62 84.81,63.79 84.61,63.58 84.52,63.58 84.43,63.5 84.41,63.5 84.41,63.48 84.36,63.42 84.36,62.67 84.35,62.66 83.36,62.66 83.28,62.74 83.28,63.34 83.6,63.67 84.27,63.67 84.49,63.88 84.49,64.6 84.58,64.7 84.74,64.7
N49227486 on BOTTOM (solid shape): 85.81,64.65 85.81,63.64 85.58,63.41 85.58,62.76 85.45,62.63 84.69,62.63 84.68,62.63 84.56,62.63 84.49,62.71 84.49,63.37 84.57,63.45 85.04,63.45 85.48,63.9 85.48,64.6 85.58,64.7 85.76,64.7
N49227488 on BOTTOM (solid shape): 85.57,61.3 83.42,61.3 83.4,61.32 83.4,61.94 83.42,61.96 85.57,61.96
N49231011 on BOTTOM (solid shape): 90.73,55.22 90.73,54.51 88.62,54.51 88.62,55.31 90.64,55.31
N49231017 on BOTTOM (solid shape): 90.46,57.89 90.46,57.06 90.86,56.66 90.86,56.02 90.79,55.95 89.85,55.95 89.78,56.02 89.78,56.64 90.15,57.01 90.15,57.87 90.26,57.98 90.37,57.98
N49231019 on BOTTOM (solid shape): 89.45,57.88 89.45,57.17 89.57,57.06 89.57,56.02 89.53,55.98 88.66,55.98 88.61,56.03 88.61,56.63 89.14,57.16 89.14,57.85 89.26,57.97 89.36,57.97

Small or netless copper shapes (teardrops, artwork), in the pictures only: 254 on TOP, 216 on BOTTOM, 6 on IN1, 3 on IN2, 3 on IN3, 3 on IN4, 1 on GND5

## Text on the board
Ref Des/Silkscreen Bottom: Tunable | M2X3 | H34 | CONN | BATT | TP | TS | USH | EDP | PWR | LED | Fan | IR | SAR | Gyro | WWAN/SSD | WLAN | SPKR
User.Comments: LA-F292P | 2017-11-14 | 2018-11-14 | DDA30 | Minjia | 1.0(A00)
Ref Des/Silkscreen Top: B | A | RTC
GND4: GND4
GND5: GND5
XSECTION_CHART: *  SURFACE - AIR 0 MIL | *  DIELECTRIC - FR-4 0.5 MIL | L1: TOP CONDUCTOR - COPPER 1.4 MIL | *  DIELECTRIC - FR-4 2 MIL | L2: GND1 PLANE - COPPER 1.2 MIL | L3: IN1 CONDUCTOR - COPPER 0.65 MIL | *  DIELECTRIC - FR-4 3 MIL | L4: GND2 PLANE - COPPER 0.65 MIL | *  DIELECTRIC - FR-4 2.65 MIL | L5: IN2 CONDUCTOR - COPPER 0.65 MIL | L6: GND3 PLANE - COPPER 0.65 MIL | L7: VCC PLANE - COPPER 0.65 MIL | L8: IN3 CONDUCTOR - COPPER 0.65 MIL | L9: GND4 PLANE - COPPER 0.65 MIL | L10: IN4 CONDUCTOR - COPPER 0.65 MIL | L11: GND5 PLANE - COPPER 1.2 MIL | L12: BOTTOM CONDUCTOR - COPPER 1.4 MIL | DESIGN CROSS SECTION CHART | ___________________________ | TOTAL THICKNESS 38.85 MIL | 1-12 | 1-2 | 2-11 | 11-12
User.40: trace Width | Width/Space | 3.15 | 3.5 | 5 | 3.4 | 2 | 2.4 | 4.1/3.2 | 3.7/3.8 | 5.1/3.2 | 3.7/3,8 | 3.47/3.3 | 2.45/3.25 | 3.27/4 | 2.54/3.8 | 2.87/3.8 | 3.02/3.3 | 2.65/4.45 | 2/4.6 | L2 | L4/L6 | L2/L4 | L7/L9 | L11 | L9/L11 | 6.16/3.2 | L10 | L3 | 1_0mm_1+10+1(1080106)(Top GND IN1 VCC IN2 VCC GND IN3 GND IN4 GND Bot)-0324_Founder.xlsx | GND1 | GND2 | GND3 | TOP | IN1 | IN2 | VCC | IN3 | IN4 | GND4 | GND5 | BOTTOM | LAYER | NAME | STACKUP: 12 LAYER | 40 ohm | 50 ohm | 70 ohm | THICKNESS=1.0mm | 85 ohm | 90 ohm | 100 ohm | ref | IMPEDANCE
User.43: FIGURE | SIZE | 4.0 | DRILL CHART: TOP to GND1 | ALL UNITS ARE IN MILS | TOLERANCE | +1.0/-1.0 | PLATED | QTY | 1439 | 11
User.45: FIGURE | SIZE | 8.0 | 4.0 | DRILL CHART: GND1 to GND5 | ALL UNITS ARE IN MILS | DRILL CHART: GND5 to BOTTOM | TOLERANCE | +3.0/-3.0 | +1.0/-1.0 | PLATED | QTY | 1431 | 2356 | 11 | 20.0 | 22.0 | 28.0 | 91.0 | 98.0 | 126.0 | 150.0 | 220.0 | 31.0 | 35.0 | 43.0 | 51.0 | 63.0 | 276.0 | 47.0x20.0 | 49.0x26.0 | 49.0x28.0 | 55.0x24.0 | 63.0x24.0 | 67.0x39.0 | 69.0x20.0 | 75.0x24.0 | 79.0x28.0 | 98.0x39.0 | 33.0x28.0 | 71.0x51.0 | DRILL CHART: TOP to BOTTOM | +2.0/-2.0 | +4.0/-4.0 | NON-PLATED | 4382 | 32 | 99 | 19 | 18 | 8 | 2 | 1 | 4 | 6 | 3 | 7
